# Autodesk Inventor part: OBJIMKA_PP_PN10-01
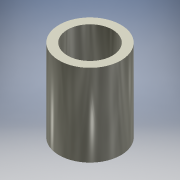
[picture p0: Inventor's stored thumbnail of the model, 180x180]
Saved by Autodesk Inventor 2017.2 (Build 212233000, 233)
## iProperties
Created: 2016-11
Part Number: OBJIMKA_PP_PN10-01
Material: Polypropylen
Document SubType Name: Modeling
Designer: CADstudio
Mass: 9.90961 g
Surface Area: 61.3288 cm^2
Volume: 11.0229 cm^3
Density: 0.899 g/cm^3
Appearance: Hladká – popel
Vendor: KOWA
Categories: <MemberInstance><Categories><Category DisplayName="" InternalName="4347fa0f-2144-441d-94cd-e3e15c92b736" Mnemonic="TUBEANDPIPE"><CategoryParameter DisplayName="
Mass: 0,01
Author: CADstudio
Title: OBJIMKA PP PN10
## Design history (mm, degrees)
sketch "Náčrt1"
  geometry: C1 r 13.75 at (0, 0); C2 r 8.1 at (0, 0); 1 further point
  constraints: 2 centre point, 2 coincident
  dimensions: "EXTERNI" = 27.5 diameter of C1; "VNI" = 16.2 diameter of C2
extrude "Vysunutí1" new body sketch "Náčrt1" taper "d3" = 0 deg; distance "H_DELKA" = 36.5
sketch "Náčrt2"
  geometry: C1 r 8.1 at (0, 0) reference; C2 r 13.75 at (0, 0) reference; C3 r 10 at (0, 0)
  constraints: 1 centre point, 1 coincident
  dimensions: "VNE" = 20 diameter of C3
extrude "Vysunutí2" cut sketch "Náčrt2" distance "d5" = 14.5 (= -0.5 x Z_MEZERA + 0.5 x H_DELKA); taper "d6" = 0 deg
sketch "Náčrt3"
  geometry: C1 r 8.1 at (0, 0) reference; C2 r 13.75 at (0, 0) reference; C3 r 10 at (0, 0)
  constraints: 1 centre point, 1 coincident
  dimensions: "d7" = 20 diameter of C3 (= VNE)
extrude "Vysunutí3" cut sketch "Náčrt3" distance "d8" = 14.5 (= -0.5 x Z_MEZERA + 0.5 x H_DELKA); taper "d9" = 0 deg
node "Pracovní bod1"
node "Pracovní bod2"
node "Pracovní osa1"
node "Těleso1"
other parameters: "Z_MEZERA" = 7.5 [user parameter; used in 2 equation terms]
